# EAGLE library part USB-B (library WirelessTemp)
USB-B Connector
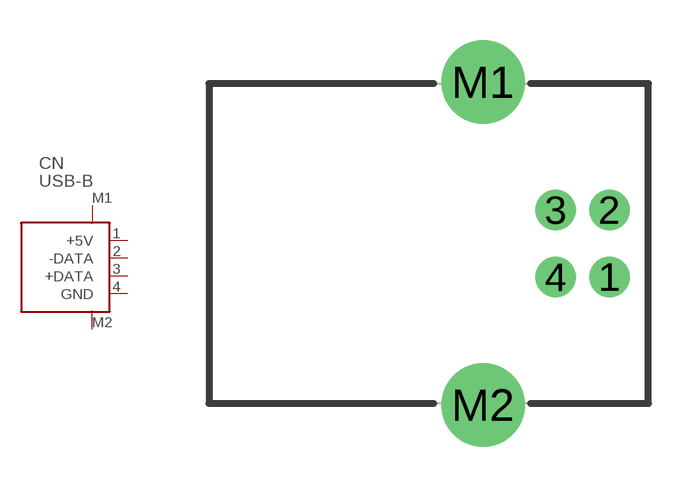
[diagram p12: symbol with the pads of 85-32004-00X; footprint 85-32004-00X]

Designator prefix CN

## USB-B  [85-32004-00X]
1  +5V  pwr
2  -DATA
3  +DATA
4  GND  pwr
M1  FG1  pas
M2  FG2  pas

## Footprint 85-32004-00X (pad centres in mm)
USB B TYPE SINGLE R/A DIP With Rear Shell, Without Rear Shell Source: http://www.cypressindustries.com/pdf/85-32004-00x.pdf
drill 1 round: 1 4.71,-1.25; 2 4.71,1.25; 3 2.71,1.25; 4 2.71,-1.25
drill 2.1 round: M1 0,6.02; M2 0,-6.02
